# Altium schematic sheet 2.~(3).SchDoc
size 420 x 297 mm
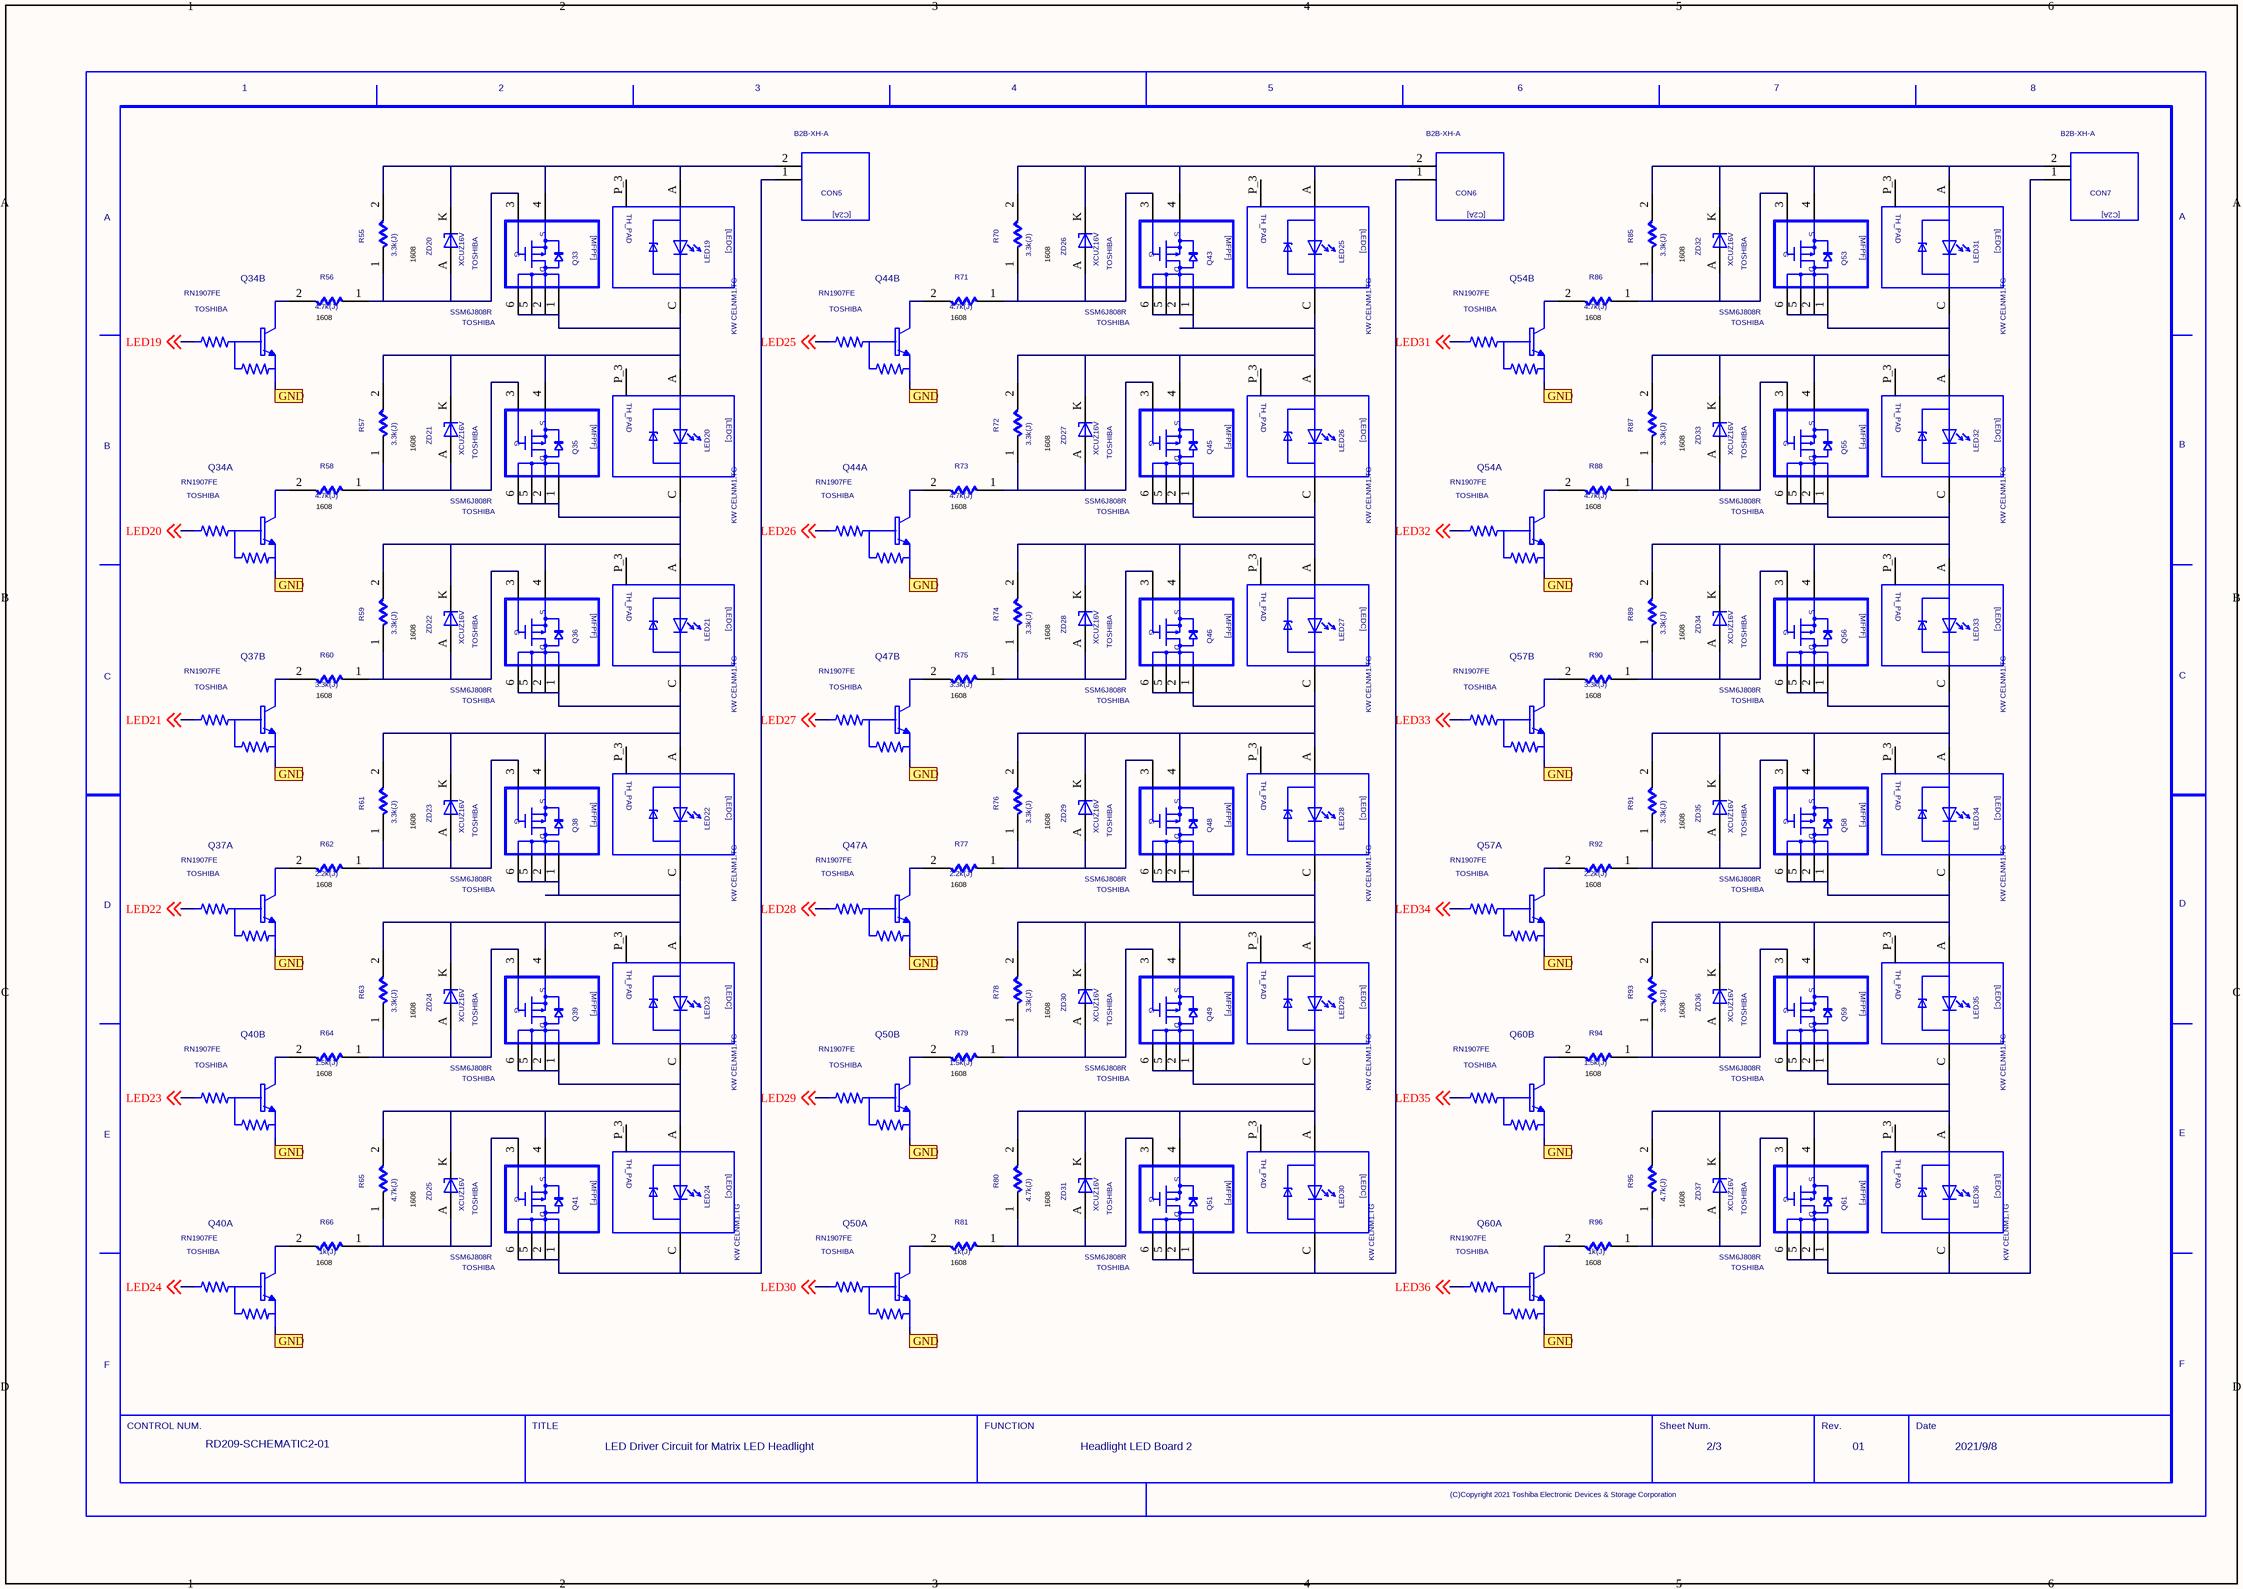
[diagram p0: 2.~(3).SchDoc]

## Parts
CON5  VAL3: B2B-XH-A  (hidden comment: C2A)
CON6  VAL3: B2B-XH-A  (hidden comment: C2A)
CON7  VAL3: B2B-XH-A  (hidden comment: C2A)
LED19  VAL3: KW CELNM1.TG  (hidden comment: LEDC)
LED20  VAL3: KW CELNM1.TG  (hidden comment: LEDC)
LED21  VAL3: KW CELNM1.TG  (hidden comment: LEDC)
LED22  VAL3: KW CELNM1.TG  (hidden comment: LEDC)
LED23  VAL3: KW CELNM1.TG  (hidden comment: LEDC)
LED24  VAL3: KW CELNM1.TG  (hidden comment: LEDC)
LED25  VAL3: KW CELNM1.TG  (hidden comment: LEDC)
LED26  VAL3: KW CELNM1.TG  (hidden comment: LEDC)
LED27  VAL3: KW CELNM1.TG  (hidden comment: LEDC)
LED28  VAL3: KW CELNM1.TG  (hidden comment: LEDC)
LED29  VAL3: KW CELNM1.TG  (hidden comment: LEDC)
LED30  VAL3: KW CELNM1.TG  (hidden comment: LEDC)
LED31  VAL3: KW CELNM1.TG  (hidden comment: LEDC)
LED32  VAL3: KW CELNM1.TG  (hidden comment: LEDC)
LED33  VAL3: KW CELNM1.TG  (hidden comment: LEDC)
LED34  VAL3: KW CELNM1.TG  (hidden comment: LEDC)
LED35  VAL3: KW CELNM1.TG  (hidden comment: LEDC)
LED36  VAL3: KW CELNM1.TG  (hidden comment: LEDC)
Q33  USERCOMPTEXT3: TOSHIBA  VAL3: SSM6J808R  (hidden comment: MFPF)
Q34  USERCOMPTEXT3: TOSHIBA  VAL3: RN1907FE  (hidden comment: RN1907FE_1)  (parts A,B of 2)
Q35  USERCOMPTEXT3: TOSHIBA  VAL3: SSM6J808R  (hidden comment: MFPF)
Q36  USERCOMPTEXT3: TOSHIBA  VAL3: SSM6J808R  (hidden comment: MFPF)
Q37  USERCOMPTEXT3: TOSHIBA  VAL3: RN1907FE  (hidden comment: RN1907FE_1)  (parts A,B of 2)
Q38  USERCOMPTEXT3: TOSHIBA  VAL3: SSM6J808R  (hidden comment: MFPF)
Q39  USERCOMPTEXT3: TOSHIBA  VAL3: SSM6J808R  (hidden comment: MFPF)
Q40  USERCOMPTEXT3: TOSHIBA  VAL3: RN1907FE  (hidden comment: RN1907FE_1)  (parts A,B of 2)
Q41  USERCOMPTEXT3: TOSHIBA  VAL3: SSM6J808R  (hidden comment: MFPF)
Q43  USERCOMPTEXT3: TOSHIBA  VAL3: SSM6J808R  (hidden comment: MFPF)
Q44  USERCOMPTEXT3: TOSHIBA  VAL3: RN1907FE  (hidden comment: RN1907FE_1)  (parts A,B of 2)
Q45  USERCOMPTEXT3: TOSHIBA  VAL3: SSM6J808R  (hidden comment: MFPF)
Q46  USERCOMPTEXT3: TOSHIBA  VAL3: SSM6J808R  (hidden comment: MFPF)
Q47  USERCOMPTEXT3: TOSHIBA  VAL3: RN1907FE  (hidden comment: RN1907FE_1)  (parts A,B of 2)
Q48  USERCOMPTEXT3: TOSHIBA  VAL3: SSM6J808R  (hidden comment: MFPF)
Q49  USERCOMPTEXT3: TOSHIBA  VAL3: SSM6J808R  (hidden comment: MFPF)
Q50  USERCOMPTEXT3: TOSHIBA  VAL3: RN1907FE  (hidden comment: RN1907FE_1)  (parts A,B of 2)
Q51  USERCOMPTEXT3: TOSHIBA  VAL3: SSM6J808R  (hidden comment: MFPF)
Q53  USERCOMPTEXT3: TOSHIBA  VAL3: SSM6J808R  (hidden comment: MFPF)
Q54  USERCOMPTEXT3: TOSHIBA  VAL3: RN1907FE  (hidden comment: RN1907FE_1)  (parts A,B of 2)
Q55  USERCOMPTEXT3: TOSHIBA  VAL3: SSM6J808R  (hidden comment: MFPF)
Q56  USERCOMPTEXT3: TOSHIBA  VAL3: SSM6J808R  (hidden comment: MFPF)
Q57  USERCOMPTEXT3: TOSHIBA  VAL3: RN1907FE  (hidden comment: RN1907FE_1)  (parts A,B of 2)
Q58  USERCOMPTEXT3: TOSHIBA  VAL3: SSM6J808R  (hidden comment: MFPF)
Q59  USERCOMPTEXT3: TOSHIBA  VAL3: SSM6J808R  (hidden comment: MFPF)
Q60  USERCOMPTEXT3: TOSHIBA  VAL3: RN1907FE  (hidden comment: RN1907FE_1)  (parts A,B of 2)
Q61  USERCOMPTEXT3: TOSHIBA  VAL3: SSM6J808R  (hidden comment: MFPF)
R55  VAL1: 3.3k(J)  (hidden comment: R)
R56  VAL1: 4.7k(J)  (hidden comment: R)
R57  VAL1: 3.3k(J)  (hidden comment: R)
R58  VAL1: 4.7k(J)  (hidden comment: R)
R59  VAL1: 3.3k(J)  (hidden comment: R)
R60  VAL1: 3.3k(J)  (hidden comment: R)
R61  VAL1: 3.3k(J)  (hidden comment: R)
R62  VAL1: 2.2k(J)  (hidden comment: R)
R63  VAL1: 3.3k(J)  (hidden comment: R)
R64  VAL1: 1.5k(J)  (hidden comment: R)
R65  VAL1: 4.7k(J)  (hidden comment: R)
R66  VAL1: 1k(J)  (hidden comment: R)
R70  VAL1: 3.3k(J)  (hidden comment: R)
R71  VAL1: 4.7k(J)  (hidden comment: R)
R72  VAL1: 3.3k(J)  (hidden comment: R)
R73  VAL1: 4.7k(J)  (hidden comment: R)
R74  VAL1: 3.3k(J)  (hidden comment: R)
R75  VAL1: 3.3k(J)  (hidden comment: R)
R76  VAL1: 3.3k(J)  (hidden comment: R)
R77  VAL1: 2.2k(J)  (hidden comment: R)
R78  VAL1: 3.3k(J)  (hidden comment: R)
R79  VAL1: 1.5k(J)  (hidden comment: R)
R80  VAL1: 4.7k(J)  (hidden comment: R)
R81  VAL1: 1k(J)  (hidden comment: R)
R85  VAL1: 3.3k(J)  (hidden comment: R)
R86  VAL1: 4.7k(J)  (hidden comment: R)
R87  VAL1: 3.3k(J)  (hidden comment: R)
R88  VAL1: 4.7k(J)  (hidden comment: R)
R89  VAL1: 3.3k(J)  (hidden comment: R)
R90  VAL1: 3.3k(J)  (hidden comment: R)
R91  VAL1: 3.3k(J)  (hidden comment: R)
R92  VAL1: 2.2k(J)  (hidden comment: R)
R93  VAL1: 3.3k(J)  (hidden comment: R)
R94  VAL1: 1.5k(J)  (hidden comment: R)
R95  VAL1: 4.7k(J)  (hidden comment: R)
R96  VAL1: 1k(J)  (hidden comment: R)
U?  DATE: 2021/9/8  REVISION: 01  SHEETNUMBER: 2/3  FUNCTION: Headlight LED Board 2  TITLE: LED Driver Circuit for / Matrix LED Headlight  DRAWINGNUMBER: RD209-SCHEMATIC2-01  (hidden comment: WAKU_DEF100)
ZD20  USERCOMPTEXT3: TOSHIBA  VAL3: XCUZ16V  (hidden comment: ZD)
ZD21  USERCOMPTEXT3: TOSHIBA  VAL3: XCUZ16V  (hidden comment: ZD)
ZD22  USERCOMPTEXT3: TOSHIBA  VAL3: XCUZ16V  (hidden comment: ZD)
ZD23  USERCOMPTEXT3: TOSHIBA  VAL3: XCUZ16V  (hidden comment: ZD)
ZD24  USERCOMPTEXT3: TOSHIBA  VAL3: XCUZ16V  (hidden comment: ZD)
ZD25  USERCOMPTEXT3: TOSHIBA  VAL3: XCUZ16V  (hidden comment: ZD)
ZD26  USERCOMPTEXT3: TOSHIBA  VAL3: XCUZ16V  (hidden comment: ZD)
ZD27  USERCOMPTEXT3: TOSHIBA  VAL3: XCUZ16V  (hidden comment: ZD)
ZD28  USERCOMPTEXT3: TOSHIBA  VAL3: XCUZ16V  (hidden comment: ZD)
ZD29  USERCOMPTEXT3: TOSHIBA  VAL3: XCUZ16V  (hidden comment: ZD)
ZD30  USERCOMPTEXT3: TOSHIBA  VAL3: XCUZ16V  (hidden comment: ZD)
ZD31  USERCOMPTEXT3: TOSHIBA  VAL3: XCUZ16V  (hidden comment: ZD)
ZD32  USERCOMPTEXT3: TOSHIBA  VAL3: XCUZ16V  (hidden comment: ZD)
ZD33  USERCOMPTEXT3: TOSHIBA  VAL3: XCUZ16V  (hidden comment: ZD)
ZD34  USERCOMPTEXT3: TOSHIBA  VAL3: XCUZ16V  (hidden comment: ZD)
ZD35  USERCOMPTEXT3: TOSHIBA  VAL3: XCUZ16V  (hidden comment: ZD)
ZD36  USERCOMPTEXT3: TOSHIBA  VAL3: XCUZ16V  (hidden comment: ZD)
ZD37  USERCOMPTEXT3: TOSHIBA  VAL3: XCUZ16V  (hidden comment: ZD)

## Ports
GND

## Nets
LED19: Q34.5 ; off-sheet LED19
LED20: Q34.2 ; off-sheet LED20
LED21: Q37.5 ; off-sheet LED21
LED22: Q37.2 ; off-sheet LED22
LED23: Q40.5 ; off-sheet LED23
LED24: Q40.2 ; off-sheet LED24
LED25: Q44.5 ; off-sheet LED25
LED26: Q44.2 ; off-sheet LED26
LED27: Q47.5 ; off-sheet LED27
LED28: Q47.2 ; off-sheet LED28
LED29: Q50.5 ; off-sheet LED29
LED30: Q50.2 ; off-sheet LED30
LED31: Q54.5 ; off-sheet LED31
LED32: Q54.2 ; off-sheet LED32
LED33: Q57.5 ; off-sheet LED33
LED34: Q57.2 ; off-sheet LED34
LED35: Q60.5 ; off-sheet LED35
LED36: Q60.2 ; off-sheet LED36
LED+4: CON5.2 LED19.A Q33.4 R55.2 ZD20.K(C)
LED+5: CON6.2 LED25.A Q43.4 R70.2 ZD26.K(C)
LED+6: CON7.2 LED31.A Q53.4 R85.2 ZD32.K(C)
LED-4: CON5.1 LED24.C Q41.1 Q41.2 Q41.5 Q41.6
SIG79: LED26.C LED27.A Q45.1 Q45.2 Q45.5 Q45.6 Q46.4 R74.2 ZD28.K(C)
SIG80: LED25.C LED26.A Q43.1 Q43.2 Q43.5 Q43.6 Q45.4 R72.2 ZD27.K(C)
SIG81: LED28.C LED29.A Q48.1 Q48.2 Q48.5 Q48.6 Q49.4 R78.2 ZD30.K(C)
SIG86: LED27.C LED28.A Q46.1 Q46.2 Q46.5 Q46.6 Q48.4 R76.2 ZD29.K(C)
SIG87: Q50.6 R81.2
SIG92: Q47.3 R75.2
SIG96: LED21.C LED22.A Q36.1 Q36.2 Q36.5 Q36.6 Q38.4 R61.2 ZD23.K(C)
SIG97: LED35.C LED36.A Q59.1 Q59.2 Q59.5 Q59.6 Q61.4 R95.2 ZD37.K(C)
SIG98: Q50.3 R79.2
SIG99: Q57.6 R92.2
SIG100: Q44.3 R71.2
SIG101: Q34.1 Q34.4 Q37.1 Q37.4 Q40.1 Q40.4 Q44.1 Q44.4 Q47.1 Q47.4 Q50.1 Q50.4 Q54.1 Q54.4 Q57.1 Q57.4 Q60.1 Q60.4 ; port GND  [also labelled SIG105, SIG113, SIG116, SIG117, SIG134, SIG136, SIG143, SIG147, SIG151, SIG154, SIG158, SIG159, SIG166, SIG171, SIG84, SIG88, SIG90]
SIG102: Q43.3 R70.1 R71.1 ZD26.A
SIG103: Q58.3 R91.1 R92.1 ZD35.A
SIG104: LED34.C LED35.A Q58.1 Q58.2 Q58.5 Q58.6 Q59.4 R93.2 ZD36.K(C)
SIG110: LED23.C LED24.A Q39.1 Q39.2 Q39.5 Q39.6 Q41.4 R65.2 ZD25.K(C)
SIG112: LED19.C LED20.A Q33.1 Q33.2 Q33.5 Q33.6 Q35.4 R57.2 ZD21.K(C)
SIG114: LED20.C LED21.A Q35.1 Q35.2 Q35.5 Q35.6 Q36.4 R59.2 ZD22.K(C)
SIG115: Q54.6 R88.2
SIG121: Q59.3 R93.1 R94.1 ZD36.A
SIG124: Q61.3 R95.1 R96.1 ZD37.A
SIG128: Q40.3 R64.2
SIG129: Q60.3 R94.2
SIG130: Q60.6 R96.2
SIG131: Q54.3 R86.2
SIG133: Q40.6 R66.2
SIG135: Q53.3 R85.1 R86.1 ZD32.A
SIG137: Q37.3 R60.2
SIG138: Q39.3 R63.1 R64.1 ZD24.A
SIG141: Q35.3 R57.1 R58.1 ZD21.A
SIG142: Q37.6 R62.2
SIG144: LED22.C LED23.A Q38.1 Q38.2 Q38.5 Q38.6 Q39.4 R63.2 ZD24.K(C)
SIG145: Q38.3 R61.1 R62.1 ZD23.A
SIG146: LED33.C LED34.A Q56.1 Q56.2 Q56.5 Q56.6 Q58.4 R91.2 ZD35.K(C)
SIG149: Q36.3 R59.1 R60.1 ZD22.A
SIG150: Q34.6 R58.2
SIG155: Q33.3 R55.1 R56.1 ZD20.A
SIG156: Q34.3 R56.2
SIG160: Q57.3 R90.2
SIG163: Q47.6 R77.2
SIG165: Q44.6 R73.2
SIG167: LED29.C LED30.A Q49.1 Q49.2 Q49.5 Q49.6 Q51.4 R80.2 ZD31.K(C)
SIG169: Q48.3 R76.1 R77.1 ZD29.A
SIG170: Q46.3 R74.1 R75.1 ZD28.A
SIG219: Q41.3 R65.1 R66.1 ZD25.A
SIG220: CON6.1 LED30.C Q51.1 Q51.2 Q51.5 Q51.6
SIG221: Q51.3 R80.1 R81.1 ZD31.A
SIG222: Q49.3 R78.1 R79.1 ZD30.A
SIG223: Q45.3 R72.1 R73.1 ZD27.A
SIG224: CON7.1 LED36.C Q61.1 Q61.2 Q61.5 Q61.6
SIG225: Q56.3 R89.1 R90.1 ZD34.A
SIG226: Q55.3 R87.1 R88.1 ZD33.A
SIG227: LED32.C LED33.A Q55.1 Q55.2 Q55.5 Q55.6 Q56.4 R89.2 ZD34.K(C)
SIG228: LED31.C LED32.A Q53.1 Q53.2 Q53.5 Q53.6 Q55.4 R87.2 ZD33.K(C)

Not connected (* = marked no-connect by the designer): LED19 P_3(NC); LED20 P_3(NC); LED21 P_3(NC); LED22 P_3(NC); LED23 P_3(NC); LED24 P_3(NC); LED25 P_3(NC); LED26 P_3(NC); LED27 P_3(NC); LED28 P_3(NC); LED29 P_3(NC); LED30 P_3(NC); LED31 P_3(NC); LED32 P_3(NC); LED33 P_3(NC); LED34 P_3(NC); LED35 P_3(NC); LED36 P_3(NC)

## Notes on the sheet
- 1608
- (near R56) 1608
- (near R71) 1608
- (near R86) 1608
- (near R58) 1608
- (near R73) 1608
- (near R88) 1608
- (near R60) 1608
- (near R75) 1608
- (near R90) 1608
- (near R62) 1608
- (near R77) 1608
- (near R92) 1608
- (near R64) 1608
- (near R79) 1608
- (near R94) 1608
- (near R66) 1608
- (near R81) 1608
- (near R96) 1608

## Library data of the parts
CON5-CON7 = C2A: SAVEAREA0: -4611,-206,24632,18258; SAVECOUNT: 25; TIME: 13:28:28; UPDATEUSER: tomizawa-y; UPDATETIME: 12:08:31; OriginalSymbolOrigin: (2540,15240)
LED19-LED36 = LEDC: SAVEAREA0: -10936,-329,35896,28705; TIME: 14:49:55; UPDATEUSER: fukuda-y; UPDATETIME: 15:53:51; SAVECOUNT: 15; OriginalSymbolOrigin: (5080,25400); COMPONENTNAME: LED; CDBNAME: KW
Q33 Q35 Q36 Q38 Q39 Q41 Q43 Q45 Q46 Q48 Q49 Q51 Q53 Q55 Q56 Q58 Q59 Q61 = MFPF: SAVECOUNT: 11; SAVEAREA0: -6011,0,28984,22860; OriginalSymbolOrigin: (5080,20320); COMPONENTNAME: TSOP6F
Q34 Q37 Q40 Q44 Q47 Q50 Q54 Q57 Q60 = RN1907FE_1: COMP: ES6; TIME: 08:46:53; UPDATEUSER: t5459927; UPDATETIME: 14:30:50; SAVECOUNT: 6; SAVEAREA0: -3836,-13019,18528,3377; OriginalSymbolOrigin: (0,5080); CaptureCellPackProp: RN1907FE_1A
R55 R64 R70 R79 R85 R94 = R: OriginalSymbolOrigin: (5080,5080); COMPONENTNAME: R0603_1; VAL2: 100mW
R56 R63 R71 R78 R86 R93 = R: OriginalSymbolOrigin: (5080,5080); COMPONENTNAME: R0603_2; VAL2: 100mW
R57 R72 R87 = R: OriginalSymbolOrigin: (5080,5080); VAL2: 100mW; COMPONENTNAME: R0603_3
R58 R60 R73 R75 R88 R90 = R: OriginalSymbolOrigin: (5080,5080); COMPONENTNAME: R0603_4; VAL2: 100mW
R59 R62 R74 R77 R89 R92 = R: OriginalSymbolOrigin: (5080,5080); COMPONENTNAME: R0603_5; VAL2: 100mW
R61 R76 R91 = R: OriginalSymbolOrigin: (5080,5080); VAL2: 100mW; COMPONENTNAME: R0603_6
R65 R80 R95 = R: OriginalSymbolOrigin: (5080,5080); VAL2: 100mW; COMPONENTNAME: R0603_7
R66 R81 R96 = R: OriginalSymbolOrigin: (5080,5080); COMPONENTNAME: R0603_8; VAL2: 100mW
U? = WAKU_DEF100: PLOTTIME: HH:MM; SAVEAREA0: 148187,-66180,486823,89919; TIME: 14:30:25; UPDATEUSER: t5459927; UPDATETIME: 14:28:22; SAVECOUNT: 6; OriginalSymbolOrigin: (10160,284480)
ZD20-ZD37 = ZD: SAVEAREA0: -4630,-153,17114,13055; TIME: 14:49:55; UPDATEUSER: fukuda-y; UPDATETIME: 08:18:42; SAVECOUNT: 6; OriginalSymbolOrigin: (5080,5080); COMPONENTNAME: USC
